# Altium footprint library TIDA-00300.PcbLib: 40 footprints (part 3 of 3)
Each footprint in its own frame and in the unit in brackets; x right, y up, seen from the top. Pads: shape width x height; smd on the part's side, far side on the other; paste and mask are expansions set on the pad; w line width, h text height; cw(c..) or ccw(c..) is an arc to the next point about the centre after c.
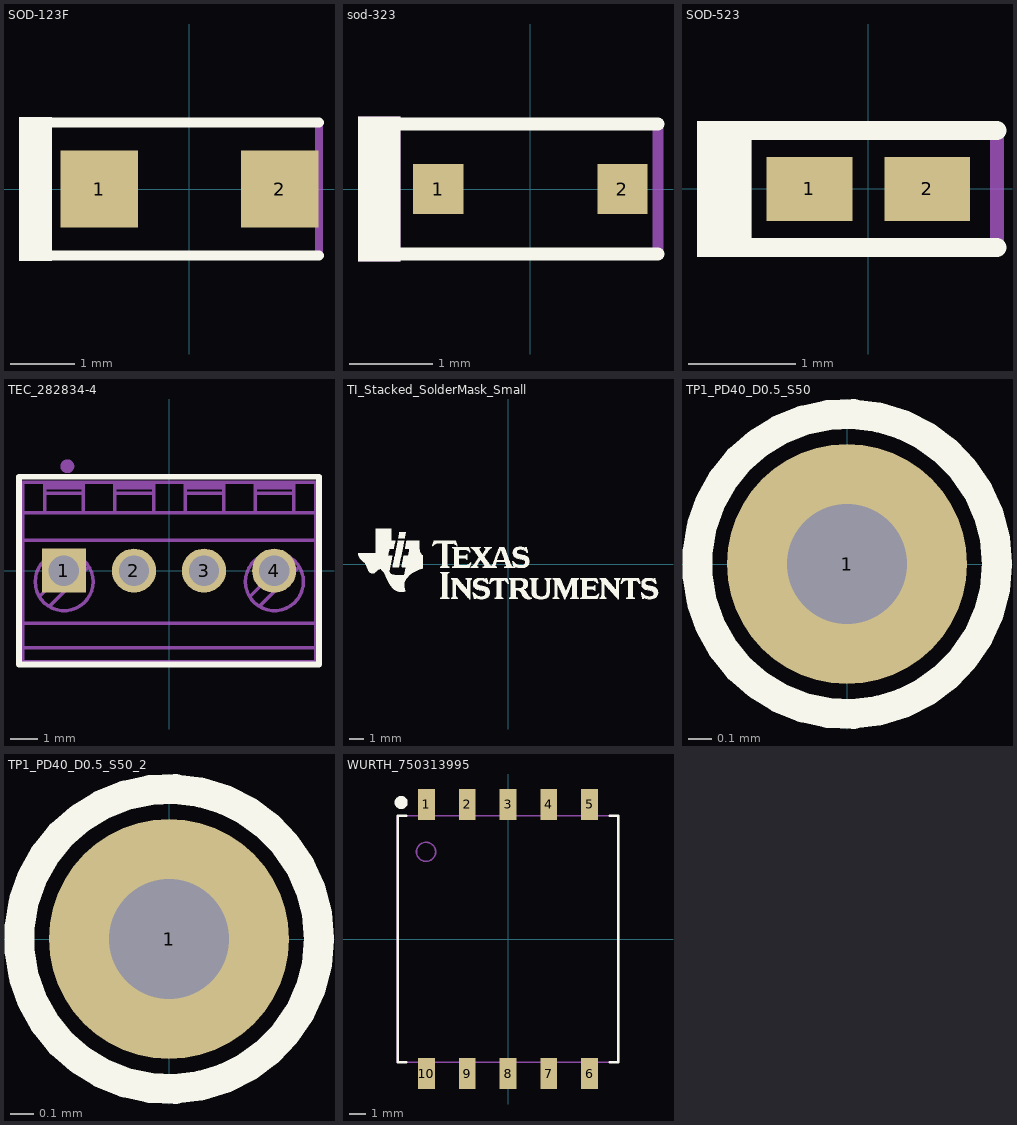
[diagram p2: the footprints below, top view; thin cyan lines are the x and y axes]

## SOD-123F [mm] "NXP recommended land pattern"
height 1.2
pads (2):
  rect 1.2x1.2 smd: 1(-1.4,0) 2(1.4,0)
Top Overlay:
  rectangle: -2.642,-1.118 -2.134,1.118
  lines w0.152: -2.311,-1.029 2.007,-1.029 ; -2.311,1.029 2.007,1.029
Mechanical 5:
  rectangle: -2.642,-1.118 -2.134,1.118
  lines w0.127: -2.311,-1.029 2.007,-1.029 2.007,1.029 -2.311,1.029
  text ".Designator" at 0.61,0.33 h0.76
3D body "SOD123F.stp": height 1.2, standoff 0, extent -1.8,-0.85 1.8,0.85

## sod-323 [mm] "NXP recommended land pattern"
height 1.1
pads (2):
  rect 0.6x0.6 smd: 1(-1.1,0) 2(1.1,0)
Top Overlay:
  rectangle: -2.057,-0.864 -1.549,0.864
  lines w0.152: -1.803,-0.775 0.1,-0.775 1.525,-0.775 ; -1.803,0.775 0.1,0.775 1.525,0.775
Mechanical 5:
  rectangle: -2.057,-0.864 -1.549,0.864
  lines w0.127: -1.803,-0.775 0.1,-0.775 1.525,-0.775 1.525,0.775 0.1,0.775 -1.803,0.775
  text ".Designator" at 0.762,0.381 h0.76
3D body "SOD-323.stp": height 1.1, standoff 0, extent -1.3,-0.675 1.3,0.675

## SOD-523 [mm] "NXP Semiconductor recommended land pattern, nominal STEP model"
height 0.7
pads (2):
  rect 0.8x0.6 smd: 1(-0.55,0) 2(0.55,0)
Top Overlay:
  rectangle: -1.598,-0.635 -1.09,0.635
  lines w0.178: -1.475,-0.546 0,-0.546 1.2,-0.546 ; -1.475,0.546 0,0.546 1.2,0.546
Mechanical 5:
  rectangle: -1.598,-0.635 -1.09,0.635
  lines w0.127: -1.475,-0.546 0,-0.546 1.2,-0.546 1.2,0.546 0,0.546 -1.475,0.546
  text ".Designator" at -1.143,-1.778 h0.76
3D body "SOD-523F.stp": height 0.72, standoff 0.02, extent -0.8,-0.399 0.8,0.399

## TEC_282834-4 [mm] "TEC"
height 10.3
pads (4):
  rect 1.6x1.6 hole 1.1: 1(-3.81,0)
  round 1.6 hole 1.1: 2(-1.27,0) 3(1.27,0) 4(3.81,0)
Top Overlay:
  lines w0.2: -5.435,-3.4 5.435,-3.4 5.435,3.4 -5.435,3.4 -5.435,-3.4
Mechanical 5:
  circle w0.3: c-3.683,3.783 r0.1
  lines w0.127: -4.698,-0.944 -3.256,0.498 ; -4.5,2.8 -3.1,2.8 ; -4.5,3 -3.1,3 ; -4.5,3.1 -3.1,3.1 ; -4.344,-1.298 -2.902,0.144 ; -1.96,2.8 -0.56,2.8 ; -1.96,3 -0.56,3 ; -1.96,3.1 -0.56,3.1 ; 0.58,2.8 1.98,2.8 ; 0.58,3 1.98,3 ; 0.58,3.1 1.98,3.1 ; 2.922,-0.944 4.364,0.498 ; 3.12,2.8 4.52,2.8 ; 3.12,3 4.52,3 ; 3.12,3.1 4.52,3.1 ; 3.276,-1.298 4.718,0.144 ; -5.3,-2.8 5.32,-2.8 ; -5.3,-2.8 -5.3,-3.3 5.32,-3.3 5.32,-2.8 ; -5.3,-2.8 -5.3,-1.9 ; -5.3,-1.9 -5.3,1.1 ; -5.3,-1.9 5.32,-1.9 ; -5.3,1.1 -5.3,2.1 ; -5.3,1.1 5.32,1.1 ; -5.3,2.1 -5.3,2.9 -5.3,3.2 -4.5,3.2 ; -5.3,2.1 -4.5,2.1 ; -4.5,2.1 -4.5,2.9 -4.5,3.2 ; -4.5,2.1 -3.1,2.1 ; -4.5,3.2 -3.1,3.2 ; -3.1,2.1 -1.96,2.1 ; -3.1,2.1 -3.1,2.9 -3.1,3.2 ; -3.1,3.2 -1.96,3.2 ; -1.96,2.1 -0.56,2.1 ; -1.96,2.1 -1.96,2.9 -1.96,3.2 ; -1.96,3.2 -0.56,3.2 ; -0.56,2.1 -0.56,2.9 -0.56,3.2 ; -0.56,2.1 0.58,2.1 ; -0.56,3.2 0.58,3.2 ; 0.58,2.1 0.58,2.9 0.58,3.2 ; 0.58,2.1 1.98,2.1 ; 0.58,3.2 1.98,3.2 ; 1.98,2.1 1.98,2.9 1.98,3.2 ; 1.98,2.1 3.12,2.1 ; 1.98,3.2 3.12,3.2 ; 3.12,2.1 4.52,2.1 ; 3.12,2.1 3.12,2.9 3.12,3.2 ; 3.12,3.2 4.52,3.2 ; 4.52,2.1 5.32,2.1 ; 4.52,2.1 4.52,2.9 4.52,3.2 ; 4.52,3.2 5.32,3.2 5.32,2.9 5.32,2.1 ; 5.32,-2.8 5.32,-1.9 ; 5.32,-1.9 5.32,1.1 ; 5.32,1.1 5.32,2.1 ; -4.85,-0.4 cw(c-3.8,-0.4) -2.75,-0.4 cw(c-3.8,-0.4) -4.85,-0.4 ; 2.77,-0.4 cw(c3.82,-0.4) 4.87,-0.4 cw(c3.82,-0.4) 2.77,-0.4
3D body "c-282834-4-c-3d.stp": height 10.02, standoff -3.38, extent -5.31,-3.25 5.31,3.25

## TI_Stacked_SolderMask_Small [mm]
Top Overlay:
  drawing of 18 lines, arcs and shapes, not listed

## TP1_PD40_D0.5_S50 [mil]
height 1.4
pads (1):
  round 40 hole 20: 1(0,0)
Top Overlay:
  circle w5: c0,0 r25

## TP1_PD40_D0.5_S50_2 [mil]
pads (1):
  round 40 hole 20: 1(0,0)
Top Overlay:
  circle w5: c0,0 r25

## WURTH_750313995 [mm] "WURTH"
height 12.7
pads (10):
  rect 1.016x1.88 smd: 1(-4.96,8.18) 2(-2.48,8.18) 3(0,8.18) 4(2.48,8.18) 5(4.96,8.18) 6(4.96,-8.18) 7(2.48,-8.18) 8(0,-8.18) 9(-2.48,-8.18) 10(-4.96,-8.18)
Top Overlay:
  circle w0.4: c-6.5,8.3 r0.2
  lines w0.152: -6.2,-7.5 -6.7,-7.5 -6.7,7.5 -6.4,7.5 -6.2,7.5 ; 6.2,-7.5 6.7,-7.5 6.7,-5.8 6.7,7.5 6.4,7.5 6.2,7.5
Mechanical 5:
  circle w0.1: c-4.983,5.3 r0.583
  lines w0.1: -5.3,-7.5 -5.3,-8.9 -4.6,-8.9 -4.6,-7.5 ; -5.3,7.5 -5.3,8.9 -4.6,8.9 -4.6,7.5 ; -2.8,-7.5 -2.8,-8.9 -2.1,-8.9 -2.1,-7.5 ; -2.8,7.5 -2.8,8.9 -2.1,8.9 -2.1,7.5 ; -0.3,-7.5 -0.3,-8.9 0.4,-8.9 0.4,-7.5 ; -0.3,7.5 -0.3,8.9 0.4,8.9 0.4,7.5 ; 2.1,-7.5 2.1,-8.9 2.8,-8.9 2.8,-7.5 ; 2.1,7.5 2.1,8.9 2.8,8.9 2.8,7.5 ; 4.6,-7.5 4.6,-8.9 5.3,-8.9 5.3,-7.5 ; 4.6,7.5 4.6,8.9 5.3,8.9 5.3,7.5 ; -6.73,-7.5 -6.73,7.5 6.73,7.5 6.73,-7.5 -6.73,-7.5
  text ".Designator" at -1.016,-0.127 h0.76
3D body: height 1.2, standoff 0, extent 4.601,7.501 5.299,8.899
3D body: height 1.2, standoff 0, extent 2.101,7.501 2.799,8.899
3D body: height 1.2, standoff 0, extent -0.299,7.501 0.399,8.899
3D body: height 1.2, standoff 0, extent 4.601,-8.899 5.299,-7.501
3D body: height 1.2, standoff 0, extent 2.101,-8.899 2.799,-7.501
3D body: height 1.2, standoff 0, extent -0.299,-8.899 0.399,-7.501
3D body: height 1.2, standoff 0, extent -2.799,7.501 -2.101,8.899
3D body: height 1.2, standoff 0, extent -5.299,7.501 -4.601,8.899
3D body: height 1.2, standoff 0, extent -2.799,-8.899 -2.101,-7.501
3D body: height 1.2, standoff 0, extent -5.299,-8.899 -4.601,-7.501
3D body: height 12.7, standoff 0, extent -6.729,-7.499 6.729,7.499
3D body: height 12.7, standoff 10, extent -5.566,4.717 -4.401,5.883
